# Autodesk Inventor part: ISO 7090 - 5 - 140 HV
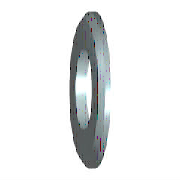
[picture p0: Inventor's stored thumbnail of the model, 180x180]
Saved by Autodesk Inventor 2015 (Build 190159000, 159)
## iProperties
Created: 2014-02
Part Number: ISO 7090 - 5 - 140 HV
Material: Stainless Steel
Description: Plain washers, charmfered - Normal series - Product grade A
Document SubType Name: Modeling
Standard: ISO 7090
Designer: rsheridan
Standard Revision: Second edition 2000-06-01
Standards Organization: ISO
Language: en-US
Size Designation: 5 - 140 HV
Categories: <MemberInstance><Categories><Category DisplayName="Fasteners" InternalName="e4da775c-781d-43d5-af7c-5136215cf5a6" Mnemonic="FSTN"><Category DisplayName="Washers
Density: 8 g/cm^3
Appearance: Semi-Polished
IsCustomPart: 1
Author: rsheridan
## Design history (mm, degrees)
sketch "Sketch"
  geometry: C1 r 5 at (0, 0); C2 r 2.65 at (0, 0); 1 further point
  constraints: 2 centre point, 2 coincident
  dimensions: "d0" = 5.3 diameter of C2 (= SD1); "d1" = 10 diameter of C1 (= SD2)
extrude "Body" new body sketch "Sketch" distance "d2" = 1 (= SD); taper "d3" = 0 deg
workaxis "Work Axis1"
workplane "Work Plane1"
body "Solid1"
chamfer "Chamfer" distance "d4" = 0.5 (= PHH); stored, may be unused: angle "d5" = 45 deg, second distance "d8" = 0.5 (= PHH)
other parameters: "SD1" = 5.3 [user parameter; used in 1 equation term], "SD2" = 10 [user parameter; used in 1 equation term], "SD" = 1 [user parameter; used in 1 equation term], "PHH" = 0.5 [user parameter; used in 2 equation terms], "FAWI" = 45 deg [user parameter], "d6" = 0, "d7" = 0, "d9" = 0, "d10" = 0, "NND" = 5 [user parameter]
